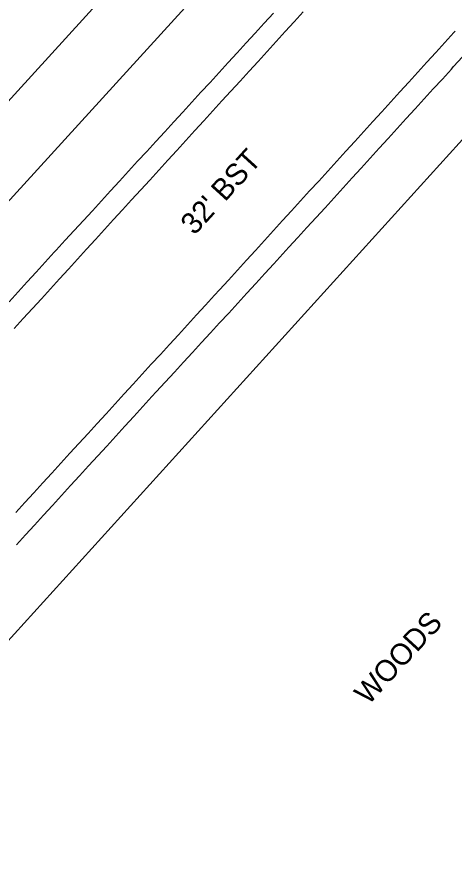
# Model space of a CAD drawing. Extents: x 1806071 to 1809844, y 912722 to 917035.
# Drawn here: x 1808619.3 to 1808701, y 915376.2 to 915532.3 of the extents above; entities that cross this region are included whole.
import ezdxf

# ---------------------------------------------------------------- set-up
doc = ezdxf.new("R2010")
doc.units = 0
for name, color, linetype in [('Exist Guardrail Cable Guide Rail', 7, 'Continuous'), ('Exist Horizontal Alignment', 7, 'Continuous'), ('Exist Roads EOP', 7, 'Continuous'), ('Exist Roads EOP Text', 7, 'Continuous'), ('Exist Roads EOT', 7, 'Continuous'), ('Exist Vegetation Woods Line', 7, 'Continuous'), ('Exist Vegetation Woods Line Text', 7, 'Continuous')]:
    doc.layers.add(name, color=color, linetype=linetype)

msp = doc.modelspace()

# ---------------------------------------------------------------- linework, layer by layer
at = {"layer": 'Exist Guardrail Cable Guide Rail'}
msp.add_lwpolyline([(1808336.06, 915188.72), (1808363.24, 915218.4), (1808387.13, 915244.72), (1808412.78, 915272.78), (1808437.24, 915299.61), (1808463.92, 915328.91), (1808487.83, 915355.26), (1808513.5, 915383.23), (1808538.93, 915411.52), (1808563.03, 915437.7), (1808575.67, 915451.68), (1808586.31, 915463.32), (1808592.39, 915469.88), (1808616.15, 915495.99), (1808637.91, 915519.85), (1808660.97, 915545.25), (1808684.67, 915571.48), (1808707.85, 915596.81)], dxfattribs=at)
at = {"layer": 'Exist Horizontal Alignment'}
msp.add_line((1806073.69, 912724.84), (1809374.2, 916346.52), dxfattribs=at)
msp.add_spline([(1808496.99, 915491.26), (1808499.1, 915492.95), (1808501.21, 915494.64), (1808503.32, 915496.33), (1808505.43, 915498.02), (1808507.54, 915499.71), (1808509.65, 915501.39), (1808511.76, 915503.08), (1808513.87, 915504.77), (1808515.98, 915506.46), (1808518.09, 915508.15), (1808520.19, 915509.85), (1808522.3, 915511.54), (1808524.41, 915513.23), (1808526.51, 915514.92), (1808528.62, 915516.62), (1808530.73, 915518.31), (1808532.83, 915520.01), (1808534.94, 915521.7), (1808537.04, 915523.4), (1808539.14, 915525.1), (1808541.24, 915526.8), (1808543.34, 915528.5), (1808545.44, 915530.2), (1808547.54, 915531.9), (1808549.64, 915533.61), (1808551.73, 915535.31), (1808553.83, 915537.02), (1808555.92, 915538.73), (1808558.02, 915540.44), (1808560.11, 915542.15), (1808562.2, 915543.87), (1808564.29, 915545.58), (1808566.38, 915547.3), (1808568.46, 915549.01), (1808570.55, 915550.73), (1808572.63, 915552.46), (1808574.71, 915554.18), (1808576.79, 915555.91), (1808578.87, 915557.63), (1808580.95, 915559.36), (1808583.02, 915561.1), (1808585.09, 915562.83), (1808587.17, 915564.57), (1808589.23, 915566.31), (1808591.3, 915568.05), (1808593.37, 915569.79), (1808595.43, 915571.54), (1808597.49, 915573.28), (1808599.55, 915575.03), (1808601.61, 915576.79), (1808603.66, 915578.54), (1808605.71, 915580.3), (1808607.76, 915582.06), (1808609.81, 915583.83), (1808611.86, 915585.59), (1808613.9, 915587.36), (1808615.94, 915589.14), (1808617.98, 915590.91), (1808620.01, 915592.69), (1808622.04, 915594.47), (1808624.07, 915596.26), (1808626.1, 915598.05), (1808628.12, 915599.84), (1808630.15, 915601.63), (1808632.16, 915603.43), (1808634.18, 915605.23), (1808636.19, 915607.04), (1808638.2, 915608.84), (1808640.21, 915610.65), (1808642.21, 915612.47), (1808644.21, 915614.29), (1808646.2, 915616.11), (1808648.2, 915617.94), (1808650.19, 915619.77)], degree=3, dxfattribs=at)
at = {"layer": 'Exist Roads EOP'}
for points in [[(1808667.24, 915532.9), (1808665.55, 915531.06), (1808663.86, 915529.21), (1808662.17, 915527.37), (1808660.48, 915525.53), (1808658.8, 915523.68), (1808657.11, 915521.84), (1808655.42, 915519.99), (1808653.73, 915518.15), (1808652.04, 915516.31), (1808650.35, 915514.46), (1808648.66, 915512.62), (1808646.98, 915510.78), (1808645.29, 915508.93), (1808643.6, 915507.09), (1808641.91, 915505.25), (1808640.22, 915503.4), (1808638.53, 915501.56), (1808636.85, 915499.72), (1808635.16, 915497.87), (1808633.47, 915496.03), (1808631.78, 915494.18), (1808630.09, 915492.34), (1808628.4, 915490.5), (1808626.71, 915488.65), (1808626.35, 915488.26), (1808624.66, 915486.41), (1808622.98, 915484.57), (1808621.29, 915482.72), (1808619.6, 915480.88), (1808617.92, 915479.03)], [(1808619.27, 915433.63), (1808620.95, 915435.48), (1808622.64, 915437.32), (1808624.33, 915439.17), (1808626.01, 915441.01), (1808627.7, 915442.86), (1808629.39, 915444.7), (1808631.08, 915446.55), (1808632.76, 915448.39), (1808634.45, 915450.24), (1808636.14, 915452.08), (1808637.83, 915453.93), (1808639.51, 915455.77), (1808641.2, 915457.62), (1808642.89, 915459.46), (1808644.57, 915461.31), (1808645.38, 915462.19), (1808647.07, 915464.03), (1808648.76, 915465.87), (1808650.45, 915467.72), (1808652.14, 915469.56), (1808653.83, 915471.4), (1808655.52, 915473.24), (1808657.21, 915475.09), (1808658.9, 915476.93), (1808660.58, 915478.77), (1808662.27, 915480.61), (1808663.96, 915482.46), (1808665.65, 915484.3), (1808667.34, 915486.14), (1808669.03, 915487.99), (1808670.15, 915489.2), (1808671.83, 915491.05), (1808673.51, 915492.9), (1808675.2, 915494.75), (1808676.88, 915496.59), (1808678.56, 915498.44), (1808680.25, 915500.29), (1808681.93, 915502.14), (1808683.61, 915503.99), (1808685.3, 915505.83), (1808686.98, 915507.68), (1808688.66, 915509.53), (1808690.35, 915511.38), (1808692.03, 915513.23), (1808693.71, 915515.08), (1808695.4, 915516.92), (1808697.08, 915518.77), (1808698.77, 915520.62), (1808700.45, 915522.47), (1808700.87, 915522.93), (1808702.55, 915524.78)]]:
    msp.add_lwpolyline(points, dxfattribs=at)
at = {"layer": 'Exist Roads EOT'}
for points in [[(1808672.8, 915533.16), (1808671.12, 915531.31), (1808669.43, 915529.47), (1808667.75, 915527.62), (1808666.06, 915525.77), (1808664.38, 915523.92), (1808662.69, 915522.08), (1808661.01, 915520.23), (1808659.32, 915518.38), (1808657.64, 915516.54), (1808655.95, 915514.69), (1808654.27, 915512.84), (1808652.59, 915510.99), (1808650.9, 915509.15), (1808649.22, 915507.3), (1808647.53, 915505.45), (1808645.85, 915503.61), (1808644.16, 915501.76), (1808642.48, 915499.91), (1808640.79, 915498.07), (1808639.11, 915496.22), (1808637.42, 915494.37), (1808635.74, 915492.52), (1808634.05, 915490.68), (1808632.37, 915488.83), (1808630.68, 915486.98), (1808629, 915485.14), (1808627.31, 915483.29), (1808625.63, 915481.44), (1808623.94, 915479.6), (1808622.26, 915477.75), (1808620.57, 915475.9), (1808618.89, 915474.05)], [(1808619.16, 915439.67), (1808620.84, 915441.52), (1808622.53, 915443.36), (1808624.22, 915445.21), (1808625.9, 915447.05), (1808627.59, 915448.9), (1808629.28, 915450.74), (1808630.96, 915452.59), (1808632.65, 915454.43), (1808634.34, 915456.28), (1808636.03, 915458.12), (1808637.71, 915459.97), (1808639.4, 915461.81), (1808641.09, 915463.66), (1808642.77, 915465.5), (1808644.46, 915467.35), (1808646.15, 915469.19), (1808647.84, 915471.04), (1808649.52, 915472.88), (1808651.21, 915474.73), (1808652.9, 915476.57), (1808654.58, 915478.42), (1808656.27, 915480.26), (1808657.17, 915481.24), (1808658.85, 915483.09), (1808660.53, 915484.94), (1808662.22, 915486.79), (1808663.9, 915488.63), (1808665.58, 915490.48), (1808667.27, 915492.33), (1808668.95, 915494.18), (1808670.63, 915496.03), (1808672.32, 915497.87), (1808674, 915499.72), (1808675.69, 915501.57), (1808677.37, 915503.42), (1808679.05, 915505.27), (1808680.74, 915507.12), (1808682.42, 915508.96), (1808684.1, 915510.81), (1808685.79, 915512.66), (1808687.47, 915514.51), (1808689.15, 915516.36), (1808690.84, 915518.2), (1808692.52, 915520.05), (1808694.21, 915521.9), (1808695.89, 915523.75), (1808697.57, 915525.6), (1808699.26, 915527.44), (1808700.94, 915529.29), (1808701.16, 915529.53)]]:
    msp.add_lwpolyline(points, dxfattribs=at)
at = {"layer": 'Exist Vegetation Woods Line'}
msp.add_lwpolyline([(1808397.76, 915010.37), (1808398.17, 915063.08), (1808401.78, 915078.95), (1808456.47, 915136.33), (1808525.87, 915216.84), (1808588.47, 915298.84), (1808603.34, 915378.8), (1808593.62, 915389.17), (1808703.69, 915510.62), (1809133.9, 915968.11), (1809176.35, 915989.33), (1809248.65, 915971.39)], dxfattribs=at)

# ---------------------------------------------------------------- texts
at = {"layer": 'Exist Roads EOP Text'}
msp.add_text("32' BST", height=4, rotation=47.671, dxfattribs=at).set_placement((1808652.51, 915491.31))
at = {"layer": 'Exist Vegetation Woods Line Text'}
msp.add_text('WOODS', height=4, rotation=47.4538, dxfattribs=at).set_placement((1808684.96, 915403.58))

doc.saveas('drawing.dxf')
